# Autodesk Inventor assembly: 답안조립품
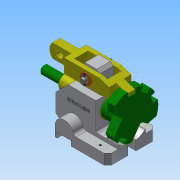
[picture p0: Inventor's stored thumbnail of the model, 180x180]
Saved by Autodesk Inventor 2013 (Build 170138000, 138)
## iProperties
Created: 2016-11
Part Number: 답안조립품
Document SubType Name: Assembly
Designer: Administrator
Author: Administrator
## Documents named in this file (8)
- C:\Users\Administrator\Desktop\461108V1007\답안조립품.iam
- C:\Users\Administrator\Desktop\461108V1007\본체.ipt
- C:\Users\Administrator\Desktop\461108V1007\부시.ipt
- C:\Users\Administrator\Desktop\461108V1007\분할대.ipt
- C:\Users\Administrator\Desktop\461108V1007\분할축.ipt
- C:\Users\Administrator\Desktop\461108V1007\와셔.ipt
- C:\Users\Administrator\Desktop\461108V1007\원통형핀.ipt
- C:\Users\Administrator\Desktop\461108V1007\클레비스핀.ipt
